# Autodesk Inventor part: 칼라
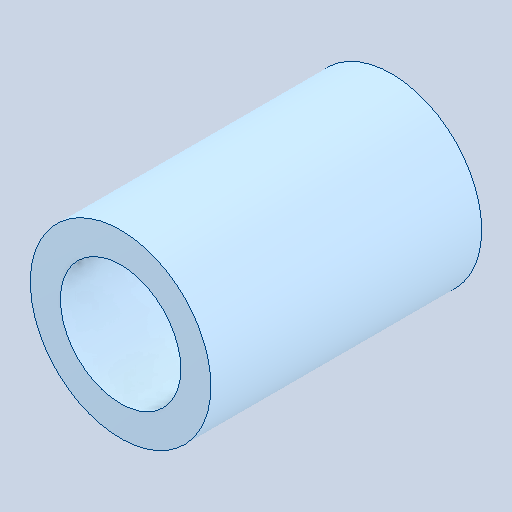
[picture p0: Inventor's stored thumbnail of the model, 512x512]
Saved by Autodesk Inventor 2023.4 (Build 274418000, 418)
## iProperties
Created: 2024-04
Part Number: 칼라
Material: 강철, 탄소
Document SubType Name: Modeling
Designer: EDU
Density: 7.87 g/cm^3
Appearance: 기본값
Author: jhkim
Sending System: Autodesk Inventor 2025
Preprocessor: ST-DEVELOPER v20
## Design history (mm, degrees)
node "칼라1"
node "솔리드2"
node "솔리드1"
